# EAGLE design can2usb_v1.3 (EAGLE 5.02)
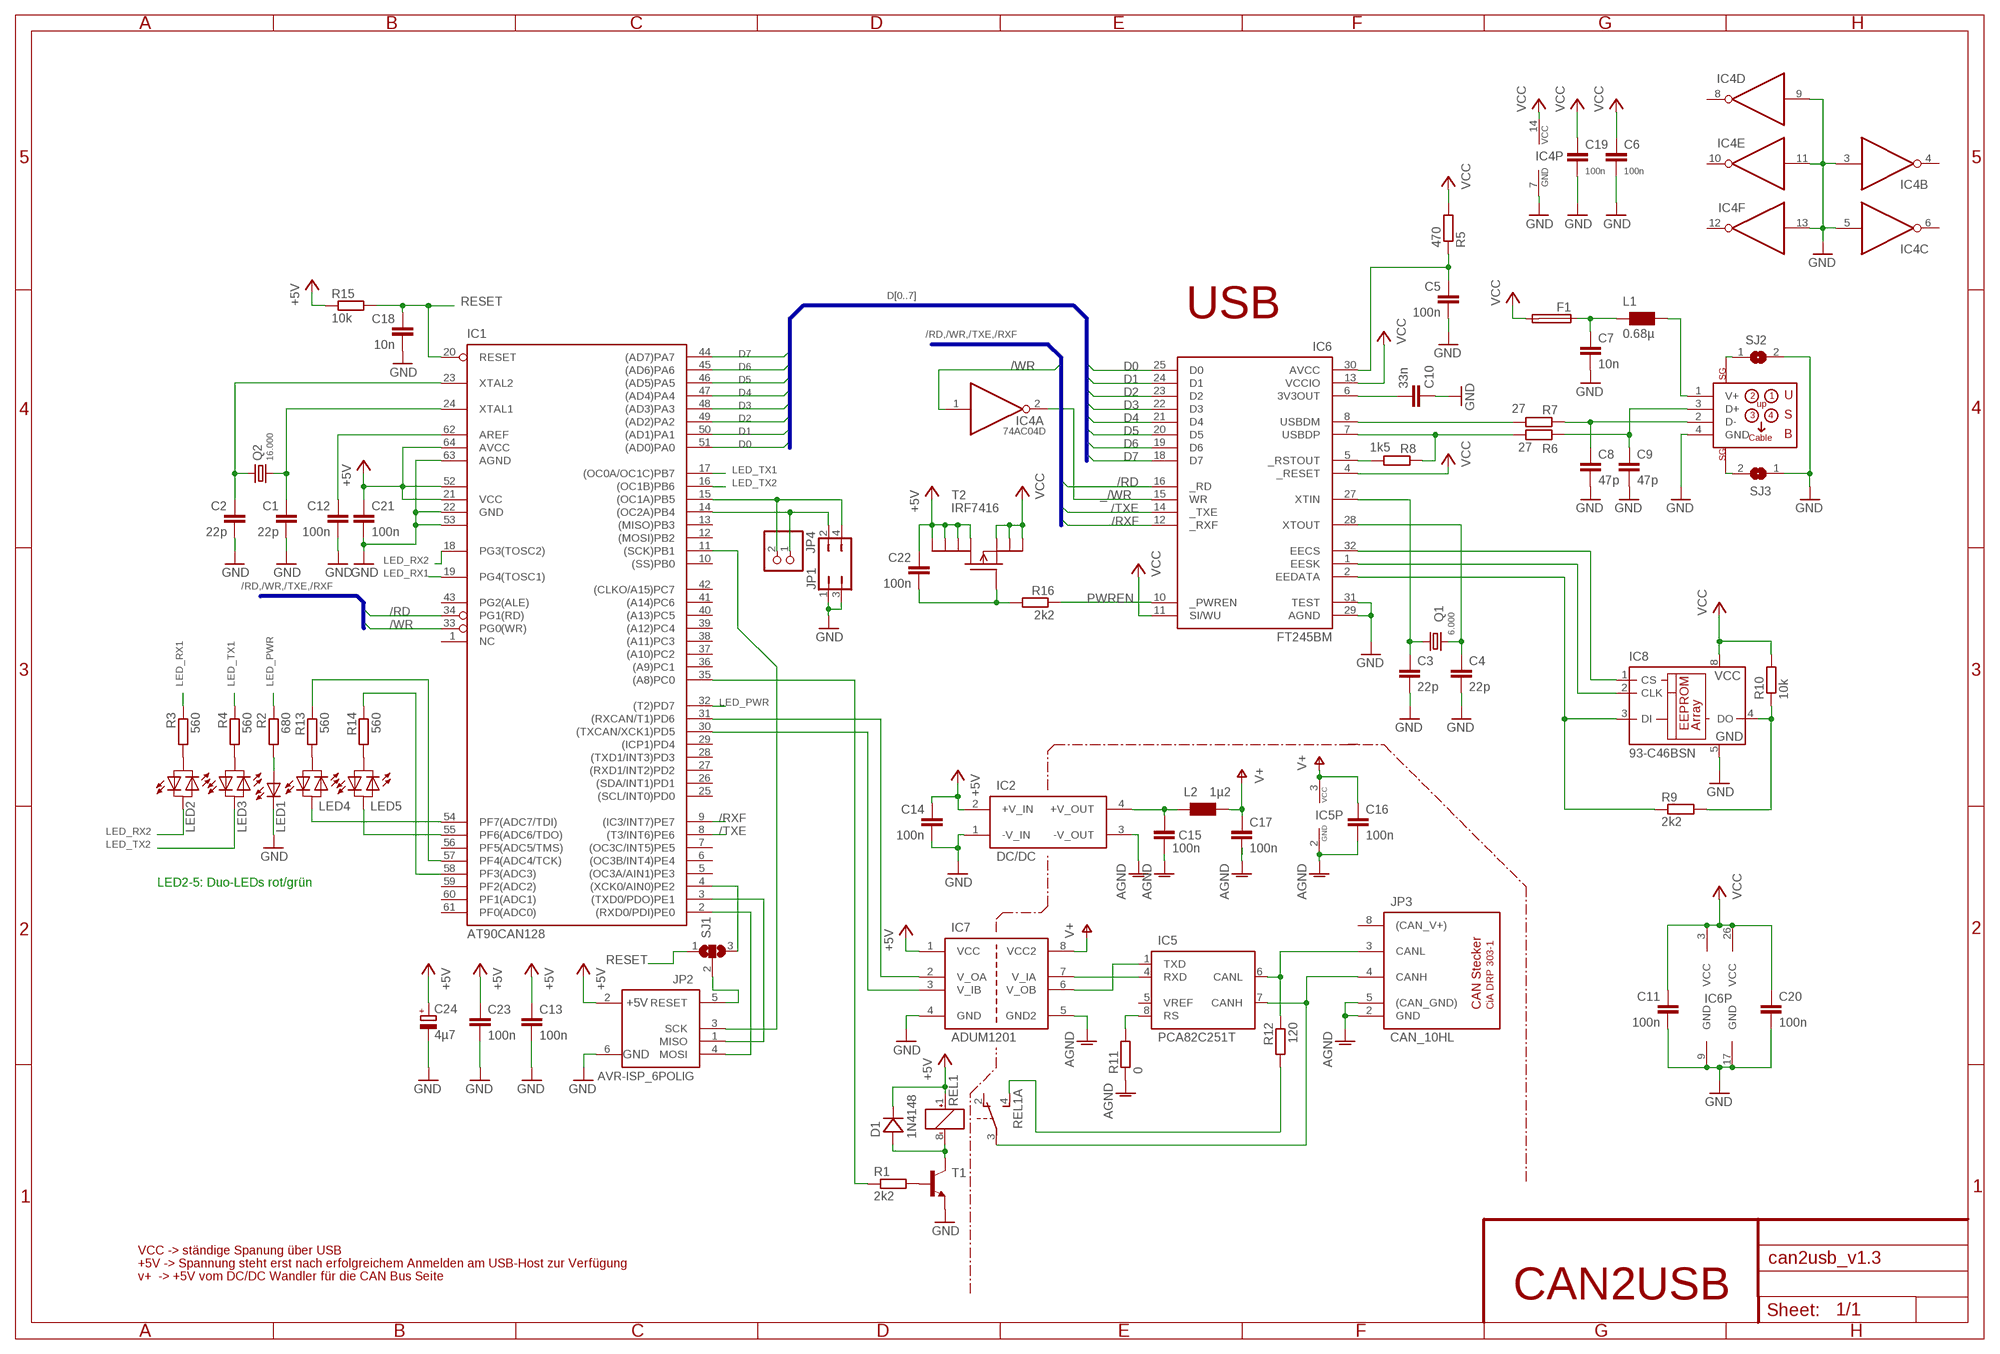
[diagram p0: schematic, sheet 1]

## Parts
C1  22p  C-EUC0805  [C0805]
C2  22p  C-EUC0805  [C0805]
C3  22p  C-EUC0805  [C0805]
C4  22p  C-EUC0805  [C0805]
C5  100n  C-EUC0805  [C0805]
C6  100n  C-EUC0805  [C0805]
C7  10n  C-EUC0805  [C0805]
C8  47p  C-EUC0805  [C0805]
C9  47p  C-EUC0805  [C0805]
C10  33n  C-EUC0805  [C0805]
C11  100n  C-EUC0805  [C0805]
C12  100n  C-EUC0805  [C0805]
C13  100n  C-EUC0805  [C0805]
C14  100n  C-EUC0805  [C0805]
C15  100n  C-EUC0805  [C0805]
C16  100n  C-EUC0805  [C0805]
C17  100n  C-EUC0805  [C0805]
C18  10n  C-EUC0805  [C0805]
C19  100n  C-EUC0805  [C0805]
C20  100n  C-EUC0805  [C0805]
C21  100n  C-EUC0805  [C0805]
C22  100n  C-EUC0805  [C0805]
C23  100n  C-EUC0805  [C0805]
C24  4µ7  CPOL-EU153CLV-0505  [153CLV-0505]
D1  1N4148  DIODESOD80C  [SOD80C]
F1  FUSE  [SMD-HASF]
IC1  AT90CAN128  AT90CAN128B  [SQFP-S-14X14-64]
IC2  DC/DC  [SIL4]
IC4  74AC04D  [SO14]
IC5  PCA82C251T  PCA82C250T  [SO08]
IC6  FT245BM  [LQFP-32]
IC7  ADUM1201  [SO08]
IC8  93-C46BSN  [SO-08]
JP1  JP2Q  [JP2Q]
JP2  AVR-ISP_6POLIG  [2X03]
JP3  CAN_10HL  [ML10L]
JP4  PINHD-1X2S  [1X02S]
L1  0.68µ  WE-KI_0805_B  [WE-KI_0805_B]
L2  1µ2  WE-KI_0805_B  [WE-KI_0805_B]
LED1  LED3MM  [LED3MM]
LED2  DUOLED  [LED3MM]
LED3  DUOLED  [LED3MM]
LED4  DUOLED  [LED3MM]
LED5  DUOLED  [LED3MM]
Q1  6.000  CRYTALSM49  [SM49]
Q2  16.000  CRYTALHC49U-V  [HC49U-V]
R1  2k2  R-EU_M0805  [M0805]
R2  680  R-EU_M0805  [M0805]
R3  560  R-EU_M0805  [M0805]
R4  560  R-EU_M0805  [M0805]
R5  470  R-EU_R0805  [R0805]
R6  27  R-EU_M0805  [M0805]
R7  27  R-EU_M0805  [M0805]
R8  1k5  R-EU_M0805  [M0805]
R9  2k2  R-EU_M0805  [M0805]
R10  10k  R-EU_M0805  [M0805]
R11  0  R-EU_M0805  [M0805]
R12  120  R-EU_R1206  [R1206]
R13  560  R-EU_M0805  [M0805]
R14  560  R-EU_M0805  [M0805]
R15  10k  R-EU_M0805  [M0805]
R16  2k2  R-EU_M0805  [M0805]
REL1  REL_2XUMDIL08SMD  [DIL08SMD]
SJ1  SJ2W  [SJ_2]
SJ2  SJ  [SJ]
SJ3  SJ  [SJ]
T1  NPNSOT23  [SOT23]
T2  IRF7416  MOSFET_P-KANAL_V1SO08  [SO08]
X1  USBCON-BB  [USBCONB]

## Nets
+5V: C13.1 C14.1 C21.1 C22.1 C23.1 C24.+ D1.C(C1) IC1.21(VCC) IC1.52(VCC1) IC1.64(AVCC) IC2.2(+V_IN) IC7.1(VCC) JP2.2(+5V) R15.1 REL1.1(SPULE:+) T2.5(D1) T2.6(D2) T2.7(D3) T2.8(D4)
/RD: IC1.34(PG1(RD)) IC6.16(_RD)
/RXF: IC1.9((IC3/INT7)PE7) IC6.12(_RXF)
/TXE: IC1.8((T3/INT6)PE6) IC6.14(_TXE)
/WR: IC1.33(PG0(WR)) IC4.1(A:I)
_/WR: IC4.2(A:O) IC6.15(WR)
_RXD: IC5.4(RXD) IC7.7(V_IA)
_TXD: IC5.1(TXD) IC7.6(V_OB)
AGND: C15.2 C16.2 C17.2 IC2.3(-V_OUT) IC5.2(GND) IC7.5(GND2) JP3.2(GND) JP3.5((CAN_GND)) R11.1
CANH: IC5.7(CANH) JP3.4(CANH) REL1.3(A:P)
CANL: IC5.6(CANL) JP3.3(CANL) R12.1
D0: IC1.51((AD0)PA0) IC6.25(D0)
D1: IC1.50((AD1)PA1) IC6.24(D1)
D2: IC1.49((AD2)PA2) IC6.23(D2)
D3: IC1.48((AD3)PA3) IC6.22(D3)
D4: IC1.47((AD4)PA4) IC6.21(D4)
D5: IC1.46((AD5)PA5) IC6.20(D5)
D6: IC1.45((AD6)PA6) IC6.19(D6)
D7: IC1.44((AD7)PA7) IC6.18(D7)
DM: C8.1 R7.1 X1.2(D-)
DP: C9.1 R6.1 X1.3(D+)
GND: C1.2 C2.2 C3.2 C4.2 C5.2 C6.2 C7.2 C8.2 C9.2 C10.1 C11.2 C12.2 C13.2 C14.2 C18.2 C19.2 C20.2 C21.2 C23.2 C24.- IC1.22(GND) IC1.53(GND1) IC1.63(AGND) IC2.1(-V_IN) IC4.3(B:I) IC4.5(C:I) IC4.7(P:GND) IC4.9(D:I) IC4.11(E:I) IC4.13(F:I) IC6.9(GND) IC6.17(GND) IC6.29(AGND) IC6.31(TEST) IC7.4(GND) IC8.5(GND) JP1.1 JP1.3 JP2.6(GND) LED1.K(C) SJ2.2 SJ3.1 T1.2(E) X1.4(GND)
LED_ERROR: IC1.57(PF4(ADC4/TCK)) R13.1
LED_OK: IC1.58(PF3(ADC3)) R14.1
LED_PWR: IC1.32((T2)PD7) R2.1
LED_RX1: IC1.19(PG4(TOSC1)) R3.1
LED_RX2: IC1.18(PG3(TOSC2)) LED2.K(C)
LED_TX1: IC1.17((OC0A/OC1C)PB7) R4.1
LED_TX2: IC1.16((OC1B)PB6) LED3.K(C)
MISO: IC1.3((TXD0/PDO)PE1) JP2.1(MISO)
N$1: JP2.5(RESET) SJ1.2
N$2: L1.1 X1.1(V+)
N$3: C22.2 R16.2 T2.4(G)
N$4: IC1.4((XCK0/AIN0)PE2) SJ1.3
N$5: R12.2 REL1.4(A:S)
N$6: D1.A(A1) REL1.8(SPULE:-) T1.3(C)
N$7: R1.2 T1.1(B)
N$8: C2.1 IC1.23(XTAL2) Q2.2
N$9: IC1.35((A8)PC0) R1.1
N$10: C1.1 IC1.24(XTAL1) Q2.1
N$11: C4.1 IC6.28(XTOUT) Q1.2
N$12: LED4.A R13.2
N$13: C3.1 IC6.27(XTIN) Q1.1
N$14: LED5.A R14.2
N$15: LED1.A R2.2
N$16: IC1.55(PF6(ADC6/TDO)) LED5.K(C)
N$17: IC1.54(PF7(ADC7/TDI)) LED4.K(C)
N$18: IC5.8(RS) R11.2
N$19: SJ2.1 X1.S2
N$20: SJ3.2 X1.S1
N$21: C7.1 F1.1 L1.2
N$22: C15.1 IC2.4(+V_OUT) L2.2
N$23: IC6.32(EECS) IC8.1(CS)
N$24: IC6.1(EESK) IC8.2(CLK)
N$25: IC8.4(DO) R9.2 R10.1
N$26: IC6.2(EEDATA) IC8.3(DI) R9.1
N$27: IC1.11((SCK)PB1) JP2.3(SCK)
N$28: C5.1 IC6.30(AVCC) R5.1
N$29: IC1.2((RXD0/PDI)PE0) JP2.4(MOSI)
N$30: C12.1 IC1.62(AREF)
N$31: IC6.8(USBDM) R7.2
N$32: IC6.7(USBDP) R6.2 R8.1
N$33: LED3.A R4.2
N$34: LED2.A R3.2
N$37: IC6.5(_RSTOUT) R8.2
N$38: C10.2 IC6.6(3V3OUT)
PWREN: IC6.10(_PWREN) R16.1
RESET: C18.1 IC1.20(RESET) R15.2 SJ1.1
RXCAN: IC1.31((RXCAN/T1)PD6) IC7.2(V_OA)
SW1: IC1.14((OC2A)PB4) JP1.2 JP4.1
SW2: IC1.15((OC1A)PB5) JP1.4 JP4.2
TXCAN: IC1.30((TXCAN/XCK1)PD5) IC7.3(V_IB)
V+: C16.1 C17.1 IC5.3(VCC) IC7.8(VCC2) L2.1
VCC: C6.1 C11.1 C19.1 C20.1 F1.2 IC4.14(P:VCC) IC6.3(VCC) IC6.4(_RESET) IC6.11(SI/WU) IC6.13(VCCIO) IC6.26(VCC) IC8.8(VCC) R5.2 R10.2 T2.1(S1) T2.2(S2) T2.3(S3)
Unconnected: IC1.1(NC) IC1.5((OC3A/AIN1)PE3) IC1.6((OC3B/INT4)PE4) IC1.7((OC3C/INT5)PE5) IC1.10((SS)PB0) IC1.12((MOSI)PB2) IC1.13((MISO)PB3) IC1.25((SCL/INT0)PD0) IC1.26((SDA/INT1)PD1) IC1.27((RXD1/INT2)PD2) IC1.28((TXD1/INT3)PD3) IC1.29((ICP1)PD4) IC1.36((A9)PC1) IC1.37((A10)PC2) IC1.38((A11)PC3) IC1.39((A12)PC4) IC1.40((A13)PC5) IC1.41((A14)PC6) IC1.42((CLKO/A15)PC7) IC1.43(PG2(ALE)) IC1.56(PF5(ADC5/TMS)) IC1.59(PF2(ADC2)) IC1.60(PF1(ADC1)) IC1.61(PF0(ADC0)) IC4.4(B:O) IC4.6(C:O) IC4.8(D:O) IC4.10(E:O) IC4.12(F:O) IC5.5(VREF) JP3.8((CAN_V+)) REL1.2(A:O) REL1.5(B:S) REL1.6(B:P) REL1.7(B:O)

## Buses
D[0..7]
/RD,/WR,/TXE,/RXF

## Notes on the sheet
- USB
- LED2-5: Duo-LEDs rot/grün
- VCC -> ständige Spanung über USB
- +5V -> Spannung steht erst nach erfolgreichem Anmelden am USB-Host zur Verfügung
- v+  -> +5V vom DC/DC Wandler für die CAN Bus Seite
- CAN2USB

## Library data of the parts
C1-C23 = rcl:C-EU: CAPACITOR, European symbol
C24 = rcl:CPOL-EU: POLARIZED CAPACITOR, European symbol
D1 = BV_dioden:DIODE
F1 = rca_sontiges:FUSE: SMD Fuse
IC1 = avr:AT90CAN128: MICROCONTROLLER 128 Kbytes FLASH 4 Kbytes SRAM 4 Kbytes EEPROM DUAL USART 8-channel 10 bit ADC CAN 2.0 A&B Interface
IC2 = rca_spgversorgung:DC/DC
IC4 = 74xx-eu:74*04: Hex INVERTER
IC5 = andereBauteile:PCA82C250: PCA82C250 CAN Bustreiber
IC6 = ftdi:FT245BM: USB FIFO 2nd Generation USB FIFO (USB <-> Parallel)
IC7 = rca_opto:ADUM1201: ADuM1201 Dual-Channel Digital Isolators zu beziehen per Sample oder bei Farnell
IC8 = microchip:93-*: Serial EEPROM 512 x 8 bit/256 x 16 bit/1 K/4 K, 5.0 V, Microwire
JP1 = jumper:JP2Q: JUMPER
JP2 = stecker-definitionen:AVR-ISP_6POLIG: ISP (In System Programming) Stecker für AVRs Über diesen Anschluß kann ein AVR mit einem Standard ISP-Kabel direkt an einen Parallelport des PC´s angeschlossen und programmiert werden.
JP3 = stecker-definitionen:CAN_: CAN Stecker nach CiA DRP 303-1
JP4 = pinhead:PINHD-1X2: PIN HEADER
L1 L2 = wuerth-elektronik:WE-KI: SMD Wire Wound Ceramic Inductor WE-KI
LED1 = led:LED: LED
LED2-LED5 = rca_opto:DUOLED
Q1 Q2 = crystal:CRYTAL: CRYSTAL
R1-R16 = rcl:R-EU_: RESISTOR, European symbol
REL1 = BV_sonstiges:REL_2XUM
SJ1 = jumper:SJ2W: SMD solder JUMPER
SJ2 SJ3 = jumper:SJ: SMD solder JUMPER
T1 = BV_transistoren:NPN
T2 = BV_transistoren:MOSFET_P-KANAL_V1
X1 = USB:USBCON-B: USB-Contector B-Type

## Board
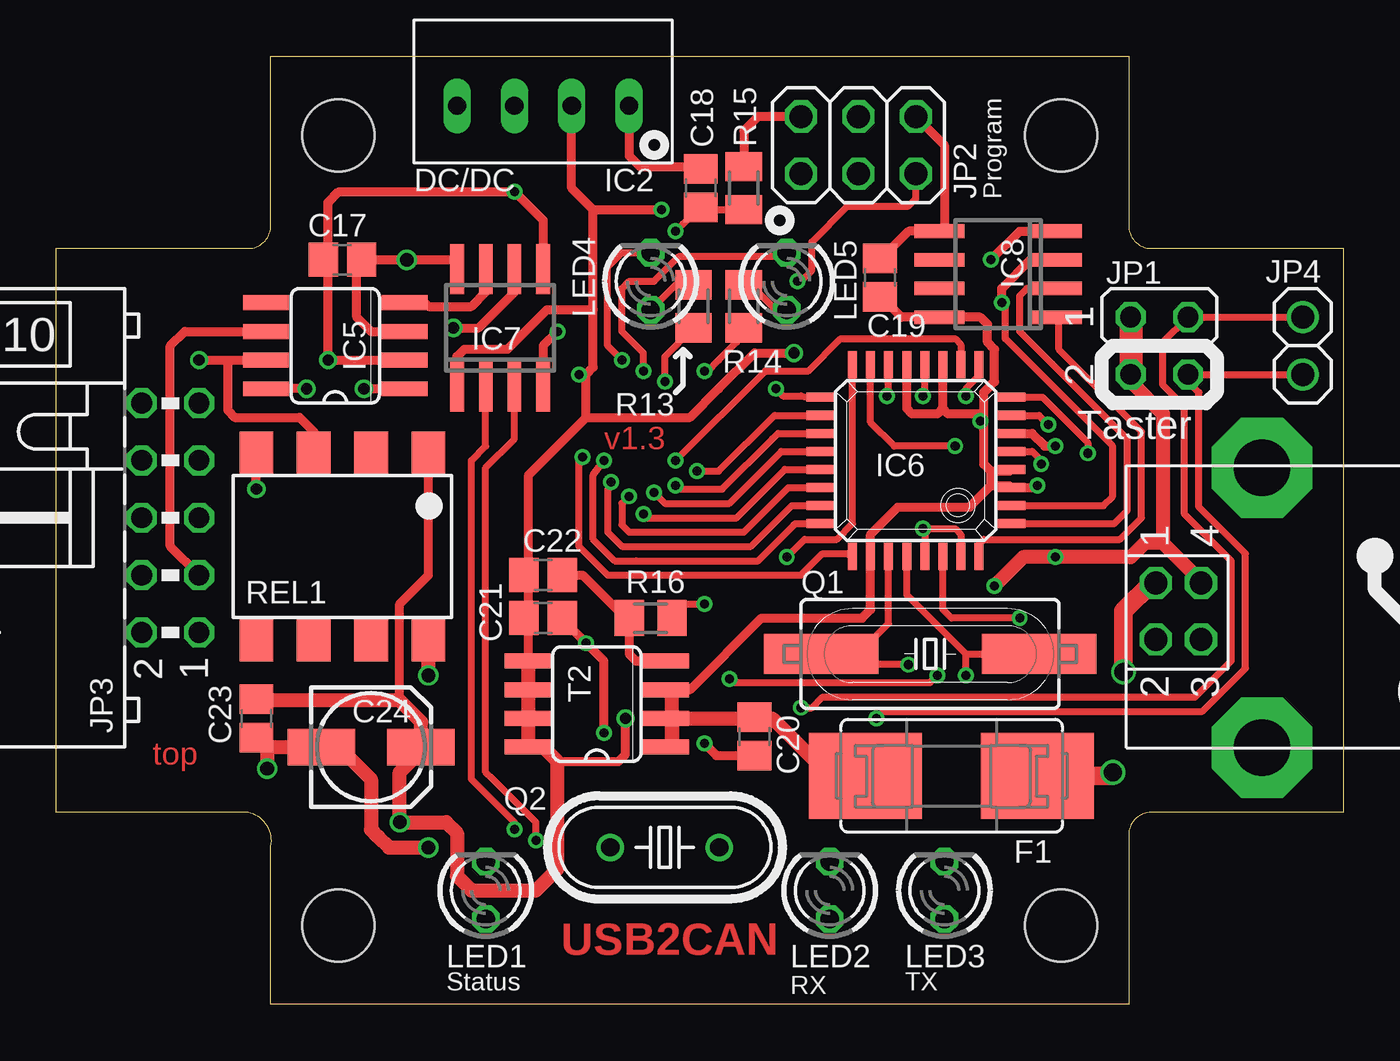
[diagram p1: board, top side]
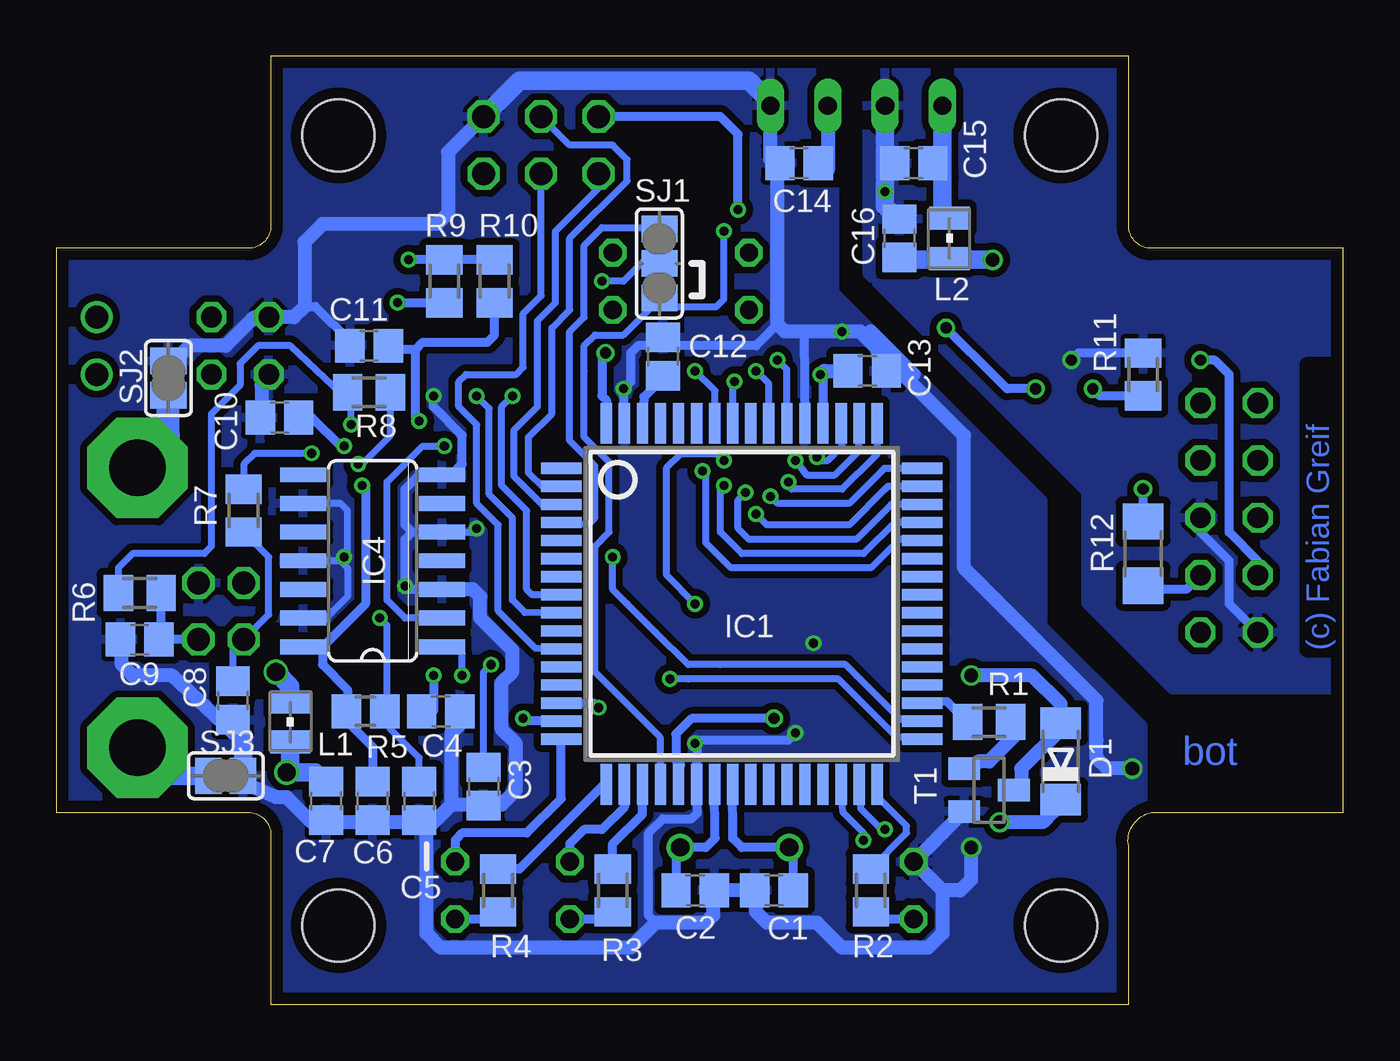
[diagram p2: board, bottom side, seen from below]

Size 57 x 42 mm. Coordinates in mm from the lower left corner, seen from the top.
Outline: 0,33.5 8.5,33.5 arc90 9.5,34.5 9.5,42 47.5,42 47.5,34.5 arc90 48.5,33.5 57,33.5 57,8.5 48.5,8.5 arc90 47.5,7.5 47.5,0 9.5,0 9.5,7 arc90 8.5,8.5 0,8.5 0,33.5
Copper layers (1*16): Top 0.035mm / dielectric 1.5mm / Bottom 0.035mm
Design rules "PCB-POOL": minimum track width 6mil, minimum drill 12mil, track to track 6mil, track to pad 6mil, pad to pad 6mil, via to via 6mil, smd to smd 6mil, copper to edge 20mil, drill to drill 8mil, minimum pad ring 8mil, minimum via ring 6mil, stop-mask expansion 3mil, vias tented up to drill 20mil, thermal gap 8mil
Holes 3.2 mm at 12.5,38.5 44.5,38.5 12.5,3.5 44.5,3.5

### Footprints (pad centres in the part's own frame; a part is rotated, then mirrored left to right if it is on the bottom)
C0805 = smd 1.3 x 1.5: 1 -0.85,0; 2 0.85,0
153CLV-0505 = smd 3 x 1.6: + 2.2,0; - -2.2,0
SOD80C = smd 1.4 x 1.8: A 1.7,0; C -1.7,0
SMD-HASF = smd 5 x 3.81: 1 -3.81,0; 2 3.81,0
SQFP-S-14X14-64 = smd 0.5 x 1.8: 1 -6,-8; 2 -5.2,-8; 3 -4.4,-8; 4 -3.6,-8; 5 -2.8,-8; 6 -2,-8; 7 -1.2,-8; 8 -0.4,-8; 9 0.4,-8; 10 1.2,-8; 11 2,-8; 12 2.8,-8; 13 3.6,-8; 14 4.4,-8; 15 5.2,-8; 16 6,-8; 33 6,8; 34 5.2,8; 35 4.4,8; 36 3.6,8; 37 2.8,8; 38 2,8; 39 1.2,8; 40 0.4,8; 41 -0.4,8; 42 -1.2,8; 43 -2,8; 44 -2.8,8; 45 -3.6,8; 46 -4.4,8; 47 -5.2,8; 48 -6,8 | smd 1.8 x 0.5: 17 8,-6; 18 8,-5.2; 19 8,-4.4; 20 8,-3.6; 21 8,-2.8; 22 8,-2; 23 8,-1.2; 24 8,-0.4; 25 8,0.4; 26 8,1.2; 27 8,2; 28 8,2.8; 29 8,3.6; 30 8,4.4; 31 8,5.2; 32 8,6; 49 -8,6; 50 -8,5.2; 51 -8,4.4; 52 -8,3.6; 53 -8,2.8; 54 -8,2; 55 -8,1.2; 56 -8,0.4; 57 -8,-0.4; 58 -8,-1.2; 59 -8,-2; 60 -8,-2.8; 61 -8,-3.6; 62 -8,-4.4; 63 -8,-5.2; 64 -8,-6
SIL4 = drill 0.813 long: 1 -3.81,0; 2 -1.27,0; 3 1.27,0; 4 3.81,0
SO14 = smd 0.66 x 2.032: 1 -3.81,-3.073; 2 -2.54,-3.073; 3 -1.27,-3.073; 4 0,-3.073; 5 1.27,-3.073; 6 2.54,-3.073; 7 3.81,-3.073; 8 3.81,3.073; 9 2.54,3.073; 10 1.27,3.073; 11 0,3.073; 12 -1.27,3.073; 13 -2.54,3.073; 14 -3.81,3.073
SO08 = smd 0.66 x 2.032: 1 -1.905,-3.073; 2 -0.635,-3.073; 3 0.635,-3.073; 4 1.905,-3.073; 5 1.905,3.073; 6 0.635,3.073; 7 -0.635,3.073; 8 -1.905,3.073
LQFP-32 = smd 0.4 x 1.2: 1 -2.8,-4.25; 2 -2,-4.25; 3 -1.2,-4.25; 4 -0.4,-4.25; 5 0.4,-4.25; 6 1.2,-4.25; 7 2,-4.25; 8 2.8,-4.25; 17 2.8,4.25; 18 2,4.25; 19 1.2,4.25; 20 0.4,4.25; 21 -0.4,4.25; 22 -1.2,4.25; 23 -2,4.25; 24 -2.8,4.25 | smd 1.2 x 0.4: 9 4.25,-2.8; 10 4.25,-2; 11 4.25,-1.2; 12 4.25,-0.4; 13 4.25,0.4; 14 4.25,1.2; 15 4.25,2; 16 4.25,2.8; 25 -4.25,2.8; 26 -4.25,2; 27 -4.25,1.2; 28 -4.25,0.4; 29 -4.25,-0.4; 30 -4.25,-1.2; 31 -4.25,-2; 32 -4.25,-2.8
SO08' = smd 0.6 x 2.2: 1 -1.905,-2.6; 2 -0.635,-2.6; 3 0.635,-2.6; 4 1.905,-2.6; 5 1.905,2.6; 6 0.635,2.6; 7 -0.635,2.6; 8 -1.905,2.6
SO-08 = smd 0.6 x 2.2: 1 -1.905,-2.6; 2 -0.635,-2.6; 3 0.635,-2.6; 4 1.905,-2.6; 5 1.905,2.6; 6 0.635,2.6; 7 -0.635,2.6; 8 -1.905,2.6
JP2Q = drill 0.914 octagon: 1 -1.27,-1.27; 2 -1.27,1.27; 3 1.27,-1.27; 4 1.27,1.27
2X03 = drill 1.016 octagon: 1 -2.54,-1.27; 2 -2.54,1.27; 3 0,-1.27; 4 0,1.27; 5 2.54,-1.27; 6 2.54,1.27
ML10L = drill 0.914 octagon: 1 -5.08,-1.27; 2 -5.08,1.27; 3 -2.54,-1.27; 4 -2.54,1.27; 5 0,-1.27; 6 0,1.27; 7 2.54,-1.27; 8 2.54,1.27; 9 5.08,-1.27; 10 5.08,1.27
1X02S = drill 1.016 round: 1 -1.27,0; 2 1.27,0
WE-KI_0805_B = smd 1.02 x 1.78: 1 -0.89,0; 2 0.89,0
LED3MM = drill 0.813 octagon: A -1.27,0; K 1.27,0
SM49 = smd 5.08 x 1.778: 1 -4.826,0; 2 4.826,0
HC49U-V = drill 0.813 round: 1 -2.413,0; 2 2.413,0
M0805 = smd 1.3 x 1.6: 1 -0.95,0; 2 0.95,0
R0805 = smd 1.3 x 1.5: 1 -0.85,0; 2 0.85,0
R1206 = smd 1.6 x 1.803: 1 -1.422,0; 2 1.422,0
DIL08SMD = smd 1.5 x 1.9: 1 -3.81,-4.15; 2 -1.27,-4.15; 3 1.27,-4.15; 4 3.81,-4.15; 5 3.81,4.15; 6 1.27,4.15; 7 -1.27,4.15; 8 -3.81,4.15
SJ_2 = smd 1.168 x 1.6: 1 -1.524,0; 2 0,0; 3 1.524,0
SJ = smd 1.168 x 1.6: 1 -0.762,0; 2 0.762,0
SOT23 = smd 1 x 1.4: 1 -0.95,-1.1; 2 0.95,-1.1; 3 0,1.1
USBCONB = drill 1.016 octagon: 1 7.3,4.7; 2 4.8,4.7; 3 4.8,2.7; 4 7.3,2.7 | drill 2.5 pad 4.445 octagon: S1 0,0; S2 12.4,0

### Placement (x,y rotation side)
C1  25.21,5.05 180 bottom
C2  28.7,5.05 0 bottom
C3  38.07,9.65 270 bottom
C4  39.97,12.99 0 bottom
C5  40.93,9.02 270 bottom
C6  42.99,9.02 270 bottom
C7  45.05,9.02 270 bottom
C8  49.18,13.46 270 bottom
C9  53.31,16.16 180 bottom
C10  47.12,26 0 bottom
C11  43.15,29.18 180 bottom
C12  30.13,28.7 90 bottom
C13  21.08,28.07 0 bottom
C14  24.1,37.28 180 bottom
C15  19.02,37.28 180 bottom
C16  19.65,33.94 90 bottom
C17  12.67,32.99 180 top
C18  28.54,36.16 90 top
C19  36.48,32.2 90 top
C20  30.92,11.88 270 top
C21  21.56,17.11 0 top
C22  21.56,19.02 0 top
C23  8.86,12.67 270 top
C24  13.94,11.4 0 top
D1  12.51,10.76 90 bottom
F1  39.66,10.13 180 top
IC1  26.64,17.75 270 bottom
IC2  21.56,39.82 180 top
IC4  42.99,19.65 90 bottom
IC5  12.35,29.18 90 top
IC6  38.07,24.1 90 top
IC7  ADUM1201  [SO08']  19.65,29.97 0 top
IC8  41.72,32.35 90 top
JP1  48.86,29.18 270 top
JP2  35.53,38.07 0 top
JP3  5.05,21.56 90 top
JP4  55.21,29.18 270 top
L1  46.64,12.51 270 bottom
L2  17.43,33.94 90 bottom
LED1  19.02,5.05 90 top
LED2  34.26,5.05 90 top
LED3  39.34,5.05 90 top
LED4  26.32,32.04 90 top
LED5  32.35,32.04 90 top
Q1  38.7,15.53 0 top
Q2  26.96,6.95 0 top
R1  15.69,12.51 0 bottom
R2  20.92,5.05 270 bottom
R3  32.35,5.05 270 bottom
R4  37.43,5.05 270 bottom
R5  43.31,12.99 180 bottom
R6  53.31,18.23 180 bottom
R7  48.7,21.88 90 bottom
R8  43.15,27.12 0 bottom
R9  39.81,32.04 90 bottom
R10  37.59,32.04 270 bottom
R11  8.86,27.91 270 bottom
R12  8.86,19.97 90 bottom
R13  28.23,30.93 90 top
R14  30.45,30.93 90 top
R15  30.45,36.16 270 top
R16  26.32,17.11 180 top
REL1  12.67,20.29 180 top
SJ1  30.29,32.83 90 bottom
SJ2  52.04,27.75 90 bottom
SJ3  49.5,10.13 180 bottom
T1  15.68,9.49 270 bottom
T2  23.94,13.3 90 top
X1  53.41,11.37 90 top

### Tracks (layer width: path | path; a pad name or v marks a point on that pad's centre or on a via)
+5V  (via drill 0.4, 0.5, 0.6)
  Top 0.406: REL1.1 16.48,19.02 15.21,17.75 15.21,13.46 | v25.21,12.67 25.21,12.19 25.21,11.08 24.89,10.76 22.19,10.76 | v25.21,12.67 | 23.46,27.91 23.78,28.23 23.78,30.77 | 23.78,30.77 23.78,35.21 | 23.78,35.21 22.83,36.16 IC2.2 22.83,40.13 | 20.92,15.21 20.92,16.8 20.61,17.11 C21.1 20.92,17.11 20.92,19.02 | 23.46,26 23.46,27.91 | 23.46,27.91 v23.15,27.91 | 29.34,27.27 28.07,26 23.46,26 | 29.34,27.27 | 29.34,27.27 30.92,28.86 v32.67,28.86 | C22.1 20.71,19.23 20.92,19.02 | 20.92,19.02 20.92,23.46 23.46,26 | 8.86,13.46 C23.1 | JP2.2 31.08,39.34 30.45,38.7 R15.1 | 23.78,35.21 v26.8,35.21 | IC7.1 17.75,28.7 18.07,29.02 19.97,29.02 21.72,30.77 23.78,30.77
  Top 0.61: 20.92,11.4 T2.8 | 20.92,11.4 20.92,12.67 | 20.92,12.67 T2.7 | 20.92,12.67 20.92,13.94 | 20.92,13.94 T2.6 | T2.5 20.92,15.21 20.92,13.94 | 20.92,11.4 21.56,11.4 22.19,10.76 22.19,6 21.24,5.05 18.38,5.05 17.75,5.68 17.75,7.59 17.27,8.06 v15.21,8.06 15.21,10.29 16.32,11.4 C24.+ 16.14,11.53 16.16,11.56 16.16,12.51 15.21,13.46 8.86,13.46
  Bottom 0.406: v25.21,12.67 28.86,12.67 29.55,11.98 29.55,10.82 29.34,10.6 29.39,10.55 IC1.21 | IC1.52 23.04,27.8 v23.15,27.91 23.1,27.86 | IC1.64 32.64,26.76 32.83,26.96 32.83,28.7 32.7,28.83 32.64,28.83 v32.67,28.86 | v26.8,35.21 26.8,38.54 27.59,39.34 JP2.2
  Bottom 0.61: C14.1 23.25,37.01 22.83,36.96 IC2.2 | D1.C 12.83,8.54 13.3,8.06 v15.21,8.06 | C13.1 22.99,28.07 v23.15,27.91
/RD  (via drill 0.4)
  Top 0.305: IC6.16 35.27,21.3 34.58,20.61 33.15,20.61 v32.35,19.81
  Bottom 0.305: IC1.34 19.62,12.63 21.56,14.57 22.03,15.05 27.59,15.05 29.02,15.05 30.45,16.48 31.72,17.75 32.35,18.38 | 32.35,18.38 v32.35,19.81 | 32.35,18.38
/RXF  (via drill 0.4)
  Top 0.305: IC6.12 38.47,27.04 v38.39,26.96
  Bottom 0.305: IC1.9 36.25,17.35 36.8,17.91 36.8,21.56 37.83,22.59 37.83,26.4 v38.39,26.96
/TXE  (via drill 0.4)
  Top 0.305: IC6.14 36.87,27.03 v36.8,26.96
  Bottom 0.305: IC1.8 35.92,18.14 36.16,18.38 36.16,21.88 37.27,22.99 37.27,26.48 v36.8,26.96
/WR  (via drill 0.4)
  Top 0.305: v29.81,14.41 29.97,14.26 33.31,14.26 33.62,14.26 38.7,14.26 v39.02,14.57
  Bottom 0.305: IC1.33 19.78,11.84 22.35,14.41 29.02,14.41 29.5,14.41 v29.81,14.41 | v39.02,14.57 39.02,15.53 39.34,15.84 IC4.1
  Bottom 0.406: IC4.1 39.66,15.84
_/WR  (via drill 0.4)
  Top 0.305: IC6.15 36.07,25.78 37.12,24.73 v39.81,24.73
  Bottom 0.305: 39.34,17.11 IC4.2 41.56,17.11 42.35,17.91 42.35,23.15 40.77,24.73 v39.81,24.73
_RXD
  Top 0.406: IC7.7 19.02,31.56 18.38,30.92 16.48,30.92 16.32,31.08 IC5.4
_TXD  (via drill 0.5)
  Top 0.406: 15.84,27.27 IC5.1 v13.62,27.27 | v17.59,29.97 18.7,29.97 20.29,31.56 IC7.6 20.29,32.67
  Bottom 0.406: v13.62,27.27 14.89,27.27 15.37,27.75 v17.59,29.97
AGND  (via drill 0.4, 0.5)
  Top 0.406: IC5.2 v12.03,28.54 12.03,32.99 | IC7.5 21.56,34.73 v20.29,36 12.51,36 12.03,35.53 12.03,32.99 | 12.03,32.99 C17.2
  Bottom 0.406: IC2.3 20.29,38.7 | JP3.2 5.05,17.75 5.05,19.65 6.32,20.92 JP3.5 | v12.03,28.54 11.72,28.86 9.02,28.86 8.86,28.7 R11.1
  Bottom 0.61: 20.29,36.64 C15.2
  Bottom 0.813: 20.29,38.86 IC2.3 20.29,36.64 v20.29,36 20.29,35.37 19.97,35.05 C16.2
  pour Bottom (isolate 0.305): -1.3,13.94 7.59,13.94 11.4,17.75 11.4,22.67 21.08,32.35 21.08,43.15 -1.3,43.15
CANH  (via drill 0.5)
  Top 0.406: v6.32,28.54 7.59,28.54 | 7.59,28.54 IC5.7 | REL1.3 11.4,25.37 10.76,26 7.91,26 7.59,26.32 7.59,28.54
  Bottom 0.406: v6.32,28.54 5.68,28.54 5.05,27.91 5.05,20.92 3.78,19.65 JP3.4
CANL
  Top 0.406: IC5.6 5.68,29.81 5.05,29.18 5.05,20.29 JP3.3
  Bottom 0.406: R12.1 8.86,18.38 6.95,18.38 JP3.3
D0  (via drill 0.4)
  Top 0.305: IC6.25 35.17,19.85 35.05,19.97 33.94,19.97 32.99,19.02 24.42,19.02 23.15,20.29 23.15,24.1 v23.3,24.26
  Bottom 0.305: IC1.51 22.31,25.48 22.19,25.37 22.19,24.73 22.83,24.1 23.15,24.1 v23.3,24.26
D1  (via drill 0.4)
  Top 0.305: IC6.24 32.73,21.3 32.67,21.24 31.08,19.65 25.69,19.65 24.73,19.65 23.78,20.61 23.78,23.46 v24.26,24.1
  Bottom 0.305: 21.56,24.42 22.51,23.46 23.78,23.46 v24.26,24.1 | 21.56,24.42 21.52,24.45 | IC1.50 21.44,24.54 21.56,24.42
D2  (via drill 0.4)
  Top 0.305: IC6.23 32.58,22.1 30.77,20.29 25.05,20.29 24.42,20.92 24.42,22.83 v24.57,23.15
  Bottom 0.305: 20.76,24.26 22.19,22.83 24.42,22.83 v24.57,23.15 | 20.76,24.26 20.73,24.29 | 20.76,24.26 | IC1.49 20.64,24.38 20.76,24.26
D3  (via drill 0.4)
  Top 0.305: IC6.22 32.42,22.9 30.45,20.92 25.37,20.92 25.05,21.24 25.05,22.19 v25.37,22.51
  Bottom 0.305: 20.42,23.65 21.88,22.19 25.05,22.19 v25.37,22.51 | IC1.48 20.32,23.75 20.42,23.65 | 20.42,23.65 | 20.42,23.65 20.45,23.62
D4  (via drill 0.4)
  Top 0.305: IC6.21 32.27,23.7 30.13,21.56 26.16,21.56 v26,21.72
  Bottom 0.305: 20.29,22.83 21.88,21.24 25.53,21.24 25.69,21.4 v26,21.72 | 20.29,22.83 20.25,22.87 | IC1.47 20.17,22.95 20.29,22.83
D5  (via drill 0.4)
  Top 0.305: IC6.20 32.12,24.5 32.04,24.42 29.81,22.19 26.96,22.19 v26.48,22.67
  Bottom 0.305: 20.13,22.03 20.09,22.08 | 20.13,22.03 21.56,20.61 26.32,20.61 26.8,21.08 26.8,22.35 v26.48,22.67 | 20.13,22.03 | IC1.46 20.02,22.15 20.13,22.03
D6  (via drill 0.4)
  Top 0.305: IC6.19 31.97,25.3 31.72,25.05 29.5,22.83 27.59,22.83 v27.43,22.99
  Bottom 0.305: v27.43,22.99 27.59,22.99 27.59,20.92 26.64,19.97 21.24,19.97 19.86,21.35 IC1.45
D7  (via drill 0.4)
  Top 0.305: IC6.18 31.81,26.1 29.34,23.62 | v28.38,23.62 29.34,23.62 | 29.34,23.62
  Bottom 0.305: IC1.44 18.92,20.5 19.02,20.61 19.65,20.61 20.92,19.34 27.11,19.34 28.23,20.45 28.23,23.3 28.23,23.46 v28.38,23.62
DM
  Bottom 0.305: R7.1 47.59,19.81 47.59,17.27 X1.2 | X1.2 | C8.1 49.18,15.68 X1.2
DP
  Bottom 0.406: X1.3 50.76,16.17 50.77,16.16 52.36,16.16 | 52.36,16.16 C9.1 | R6.1 52.36,16.16
GND  (via drill 0.4, 0.6)
  Top 0.305: 38.47,20.85 IC6.29 | 38.47,20.85 38.7,21.08 39.81,21.08 40.07,20.83 IC6.31 | IC6.17 33.25,26.9 32.99,26.96 32.19,26.96 v31.88,27.27 | IC6.9 40.87,27.85 40.29,27.27 v40.29,26.96 | 38.47,20.85 38.46,20.85 v38.39,21.08
  Top 0.406: v22.19,29.81 21.56,29.18 IC7.4 | C18.2 28.54,37.12 25.84,37.12 25.37,37.59 IC2.1 | v24.26,12.03 24.26,15.21 v23.46,16 22.51,16.95 C21.2 | JP2.6 39.34,38.07 39.34,34.42 39.18,34.26 IC8.5 37.75,34.26 36.48,32.99 | 36.48,32.99 | 36.48,32.99 C19.2 | JP1.3 47.59,27.59 | C20.2 29.23,11.02 v28.7,11.56
  Top 0.61: 50.73,18.67 X1.4 | 50.77,18.7 49.02,20.45 | 47.59,27.59 49.02,26.16 49.02,20.45 | 49.02,20.45 48.23,20.45 47.59,19.81 v44.26,19.81 42.83,19.81 v41.56,18.54 | C23.2 8.91,11.82 9.33,11.4 | 9.33,11.4 C24.- 12.51,11.4 13.94,9.97 13.94,7.75 14.26,7.43 14.73,6.95 v16.48,6.95 | 9.33,11.4 v9.33,10.45
  Top 0.813: 50.77,18.7 50.73,18.67
  Top 1.016: 47.43,30.45 | JP1.1 47.43,30.45 | JP1.3 | JP1.3 47.59,30.29 47.43,30.45
  Bottom 0.305: IC1.63 31.92,25.65 31.88,25.69 | 39.34,20.92 IC4.5 39.97,20.92 38.54,20.92 v38.39,21.08 | 40.93,23.46 39.5,23.46 | IC4.9 44.42,22.19 44.1,21.88 44.1,19.97 44.42,19.65 | 44.42,19.65 IC4.11 | IC4.13 45.05,17.11 44.1,18.07 44.1,19.34 44.42,19.65 | v44.26,19.81 | v44.26,19.81 44.42,19.65
  Bottom 0.406: 31.88,25.69 v31.88,27.27 31.56,27.59 31.56,28.86 31.24,29.18 30.45,29.18 | 30.45,29.18 C12.2 | v24.26,12.03 24.57,11.72 28.54,11.72 v28.7,11.56 28.61,11.34 IC1.22 28.61,8.48 28.86,8.22 30.13,8.22 30.77,7.59 30.77,3.94 30.45,3.62 | 25.05,30.13 26,29.18 30.45,29.18 | 24.1,29.81 23.88,29.6 IC1.53 | 39.97,18.38 41.4,18.38 v41.56,18.54 41.56,20.61 41.24,20.92 | 41.24,20.92 39.97,20.92 | IC4.7 40.93,23.46 41.56,22.83 41.56,21.24 41.24,20.92 | v40.29,26.96 40.29,26.48 39.02,25.21 39.02,23.94 39.5,23.46 | 41.24,20.92 | 45.37,8.06 45.05,8.08 | 45.05,8.08 C6.2 | 46.01,30.92 45.53,30.92 43.94,29.34 C11.2 | 45.05,8.08 45.05,8.22 C7.2 | JP1.3
  Bottom 0.61: 49.18,12.03 48.86,12.03 48.74,11.91 48.7,11.87 48.7,9.81 47.28,9.18 46.8,9.18 45.69,8.06 45.37,8.06 41.72,8.06 41.4,8.06 C5.2 40.93,8.07 40.93,8.06 40.61,7.75 | 49.18,12.03 51.88,14.57 53.63,14.57 54.1,15.05 54.1,15.84 54.26,16.16 C9.2 | 31.56,2.51 39.97,2.51 40.61,3.14 40.61,7.75 | 31.56,2.51 30.45,3.62 28.23,3.62 27.91,3.94 27.91,5.05 C2.2 C1.2 26,5.05 26,4.1 25.53,3.62 23.3,3.62 22.19,2.51 18.38,2.51 17.75,3.14 17.75,5.05 | 31.56,2.51 | 17.75,5.05 LED1.K | LED1.K | LED1.K 18.22,7.11 | JP2.6 39.66,37.75 39.66,35.05 40.13,34.58 45.21,34.58 46.01,33.78 46.01,30.92 46.48,30.45 JP1.1 | IC4.3 39.97,18.38 38.54,18.38 38.23,18.07 38.23,17.11 36.8,15.68 36.8,14.73 37.27,14.26 37.27,12.19 36.64,11.56 36.64,9.49 37.27,8.86 38.07,8.86 C3.2 38.33,8.8 | 49.18,12.35 49.18,12.03 | C10.1 47.91,26 47.91,27.43 47.59,27.75 JP1.3 | 25.21,37.27 25.37,37.43 IC2.1 | 25.21,37.27 25.05,37.59 25.05,30.13 24.73,29.81 24.1,29.81 v22.19,29.81 21.4,29.81 19.65,28.07 | C14.2 24.95,36.7 25.21,37.27 | 16.8,19.34 16.8,25.21 19.65,28.07 | 51.75,28.51 51.09,29.18 49.5,29.18 48.39,30.29 | 48.39,30.29 | 48.39,30.29 48.23,30.45 JP1.1 | JP1.1 | 40.61,7.75 39.5,8.86 | C4.2 38.96,13.25 38.86,12.67 39.5,12.03 39.5,8.86 | 40.61,7.75 | 38.33,8.8 37.97,8.8 | 38.33,8.8 38.23,8.86 39.5,8.86 | 18.22,7.11 | 18.22,7.11 17.75,7.59 | T1.2 17.26,8.08 17.75,7.59 | 17.75,7.59 | v16.48,6.95 16.48,5.52 16.95,5.05 17.75,5.05 | 16.8,19.34 | 16.8,19.34 10.92,13.46 10.92,11.72 10.92,10.92 10.45,10.45 v9.33,10.45 | 19.65,28.07 | 19.65,28.07 C13.2 20.13,28.07 | 19.02,27.91 20.92,29.81 20.29,27.91 20.13,28.07 | 20.13,28.07 19.97,28.23
  Bottom 0.813: IC2.1 25.37,39.97 26.32,40.93 36.48,40.93 JP2.6 | 54.1,15.84 54.1,16.16 | C8.2 49.18,12.35 48.74,11.91 SJ3.1
  pour Bottom (isolate 0.305, rank 2): 22.51,43.15 58.39,43.15 58.39,-1.3 8.86,-1.3 8.86,12.35 13.3,16.8 13.3,22.35 22.51,31.56
LED_ERROR  (via drill 0.4)
  Top 0.305: R13.1 26.95,28.7 v26.96,27.59
  Bottom 0.305: IC1.57 27.03,27.51
  Bottom 0.406: 27.03,27.51 v26.96,27.59
LED_OK  (via drill 0.4)
  Top 0.305: 29.34,28.54 30.13,29.34 R14.1 | 29.34,28.54 28.86,28.07 v28.7,28.07 | 29.34,28.54
  Bottom 0.305: IC1.58 27.82,27.18 v28.7,28.07
LED_PWR
  Bottom 0.305: IC1.32 20.57,9.14 19.34,7.91 19.34,7.59 R2.1
LED_RX1
  Bottom 0.406: IC1.19 31.04,8.43 32.35,7.11 R3.1
LED_RX2
  Bottom 0.406: IC1.18 31.84,8.74 32.83,7.75 33.62,7.75 34.26,7.11 LED2.K
LED_TX1
  Bottom 0.406: IC1.17 32.81,9.67 33.78,8.7 34.73,7.75 36.48,6 R4.1
LED_TX2
  Bottom 0.406: IC1.16 34.64,9.11 36.16,7.59 39.02,7.59 39.34,7.27 LED3.K
MISO
  Bottom 0.305: IC1.3 35.41,22.08 36.72,23.38 36.72,25.45 35.69,26.48 35.69,30.29 34.89,31.08 34.89,34.26 32.99,36.16 JP2.1
N$1  (via drill 0.4)
  Top 0.305: v32.83,32.04 32.99,32.04 33.46,32.51 33.46,33.78 35.05,35.37 37.75,35.37 38.07,35.69 JP2.5
  Bottom 0.305: SJ1.2 30.92,32.99 31.88,32.04 v32.83,32.04
N$2  (via drill 0.8)
  Top 0.813: v47.28,14.73 47.28,17.43 48.55,18.7 48.7,18.7 48.71,18.7 X1.1
  Bottom 0.813: L1.1 46.64,14.1 v47.28,14.73 | v47.28,14.73
N$3
  Top 0.406: R16.2 24.89,17.43 23.3,19.02 C22.2 | T2.4 25.69,15.21 25.37,15.53 R16.2 | R16.2
N$4
  Bottom 0.305: IC1.4 33.41,21.29 33.15,21.56 33.15,23.86 33.62,24.34 34.26,24.97 34.26,29.81 33.62,30.45 33.62,33.62 32.83,34.42 30.13,34.42 | 30.13,34.42 SJ1.3 | 30.13,34.42
N$5  (via drill 0.5)
  Top 0.406: v8.86,22.83 REL1.4
  Bottom 0.406: R12.2 v8.86,22.83
N$6  (via drill 0.6)
  Top 0.406: REL1.8 16.48,16.48
  Top 0.61: v16.48,14.57 REL1.8
  Bottom 0.61: 12.51,12.35 12.51,12.19 | T1.3 14.26,9.49 14.26,10.45 12.51,12.19 | 12.51,12.19 | v16.48,14.57 13.78,14.57 12.51,13.3 12.51,12.35 | D1.A 12.51,12.35
N$7
  Bottom 0.61: T1.1 16.48,10.44 16.16,10.76 15.68,10.76 14.57,11.87 14.57,12.51 | 14.57,12.51 | R1.2 14.57,12.51
N$8
  Bottom 0.406: IC1.23 27.82,7.36 28.23,6.95 29.34,6.95 | 29.34,6.95 Q2.2 | C2.1 29.55,6.74 29.34,6.95
N$9
  Bottom 0.406: R1.1 16.95,12.83 17.55,13.42 IC1.35
N$10
  Bottom 0.406: IC1.24 27.03,7.35 26.64,6.95 24.57,6.95 | Q2.1 24.57,6.95 | C1.1 24.36,6.74 24.57,6.95
N$11  (via drill 0.4)
  Top 0.305: IC6.28 37.67,18.15 40.29,15.53 | 40.29,15.53 Q1.2 | v40.29,14.57 40.29,15.53
  Bottom 0.406: C4.1 40.29,12.99 v40.29,14.57
N$12
  Top 0.305: R13.2 27.43,31.88 LED4.A
N$13  (via drill 0.4)
  Top 0.305: 36.32,15.05 v37.75,15.05 36.32,15.05 | 36.32,15.05 35.85,15.53 Q1.1 | 36.32,15.05 36,15.37 36,16 36.87,16.87 IC6.27
  Bottom 0.305: v37.75,15.05 38.07,14.73 38.07,10.76 38.23,10.6 C3.1
N$14
  Top 0.305: R14.2 30.77,31.88 31.88,30.77 LED5.A
N$15
  Bottom 0.406: R2.2 20.61,3.78 LED1.A
N$16  (via drill 0.4)
  Top 0.305: v26,28.07 26,28.86 25.05,29.81 25.05,31.72 25.37,32.04 26.48,32.04 27.59,33.15 32.19,33.15 LED5.K
  Bottom 0.305: IC1.55 25.44,27.5 v26,28.07
N$17  (via drill 0.4)
  Top 0.305: v25.05,28.54 24.42,29.18 24.42,32.67 25.05,33.31 LED4.K
  Bottom 0.305: IC1.54 24.64,28.13 v25.05,28.54
N$18  (via drill 0.5)
  Top 0.406: v11.08,27.27 IC5.8
  Bottom 0.406: v11.08,27.27 10.76,26.96 R11.2
N$19
  Bottom 1.016: X1.S2 53.45,23.77 53.47,23.78 52.04,25.21 SJ2.1
N$20
  Bottom 0.813: X1.S1 53.34,11.37 53.31,11.4 52.04,10.13 SJ3.2
N$21  (via drill 0.8)
  Top 0.813: v46.8,10.29 46.64,10.13 F1.1
  Bottom 0.813: L1.2 46.64,10.45 v46.8,10.29 45.53,10.29 45.05,9.81 C7.1
N$22
  Bottom 0.61: 17.75,36.64 C15.1
  Bottom 0.813: 17.75,38.86 IC2.4 17.75,36.64 17.75,35.21 17.59,35.05 L2.2
N$23
  Top 0.305: IC6.32 40.87,20.39 41.08,20.61 47.12,20.61 47.91,21.4 | 47.91,21.4 | 47.91,21.4 48.07,21.56 48.07,25.37 44.42,29.02 44.42,30.29 44.32,30.39 IC8.1
N$24
  Top 0.305: IC6.1 46.86,21.3 47.43,21.88 47.43,25.05 45.53,26.96 | 45.53,26.96 | 45.53,26.96 42.67,29.81 42.67,31.4 42.99,31.72 IC8.2
N$25  (via drill 0.4)
  Top 0.406: IC8.4 42.67,34.26 v41.4,32.99
  Bottom 0.406: R9.2 v41.4,32.99 | R9.2 39.66,32.99 R9.2 | R10.1 R9.2
N$26  (via drill 0.4)
  Top 0.305: IC6.2 46.39,22.1 46.8,22.51 46.8,24.73 42.04,29.5 42.04,30.92 v41.88,31.08
  Top 0.406: IC8.3 43.15,32.99 41.88,31.72 v41.88,31.08
  Bottom 0.406: R9.1 41.72,31.09 v41.88,31.08
N$27
  Bottom 0.305: IC1.11 35.78,15.78 37.43,17.43 37.43,21.24 38.39,22.19 38.39,25.69 39.18,26.48 39.18,27.59 38.86,27.91 36.64,27.91 36.32,28.23 36.32,30.61 35.53,31.4 JP2.3
N$28  (via drill 0.4)
  Top 0.305: v42.67,17.11 39.66,17.11 39.27,17.5 IC6.30
  Bottom 0.305: v42.67,17.11 42.35,16.8 42.35,13.46 42.2,12.83 | 42.2,12.83 R5.1 | C5.1 40.93,10.92 42.2,12.19 42.2,12.83 | 42.2,12.83
N$29
  Bottom 0.305: JP2.4 34.26,38.07 32.35,38.07 31.72,37.43 31.72,36.48 34.26,33.94 34.26,30.77 35.05,29.97 35.05,26.16 36.08,25.13 36.08,23.54 35.41,22.87 IC1.2
N$30
  Bottom 0.406: C12.1 29.97,27.91 30.97,26.91 IC1.62
N$31  (via drill 0.4)
  Top 0.305: IC6.8 43.68,26.9 45.69,24.89 v45.69,24.42
  Bottom 0.305: 48.7,23.94 R7.2 | v45.69,24.42 48.23,24.42 48.7,23.94 | 48.7,23.94
N$32  (via drill 0.4)
  Top 0.305: IC6.7 43.53,26.1 v43.94,25.69
  Bottom 0.305: R6.2 54.26,19.34 53.78,19.81 | 53.78,19.81 | 53.78,19.81 53.63,19.97 50.45,19.97 50.13,20.29 50.13,26.16 48.86,27.43 48.86,28.38 48.07,29.18 46.64,29.18 43.94,26.64 v43.94,25.69 43.94,26.95 R8.1
N$33
  Bottom 0.406: R4.2 37.75,3.78 LED3.A
N$34
  Bottom 0.406: R3.2 32.67,3.78 LED2.A
N$37  (via drill 0.4)
  Top 0.305: IC6.5 43.22,24.5 43.62,24.1 v43.62,23.94
  Bottom 0.305: R8.2 42.2,25.21 43.47,23.94 v43.62,23.94
N$38  (via drill 0.4)
  Top 0.406: IC6.6 43.22,25.3 43.78,24.73 v44.26,24.73
  Bottom 0.406: v44.26,24.73 44.42,24.73 45.69,26 46.01,26 C10.2
PWREN  (via drill 0.4)
  Top 0.305: R16.1 27.27,17.43 27.59,17.75 v28.7,17.75 | v27.43,24.1 31.4,28.07 33.31,28.07 34.73,29.5 39.81,29.5 40.07,29.24 IC6.10
  Bottom 0.305: v28.7,17.75 29.97,19.02 29.97,23.78 29.34,24.42 27.75,24.42 v27.43,24.1
RESET  (via drill 0.4)
  Top 0.305: R15.2 30.76,35.21 30.77,35.21 | R15.2 28.54,35.21 | 28.54,35.21 C18.1 | R15.2 28.55,35.21 28.54,35.21 | 28.54,35.21 28.38,35.21 27.75,34.58 v27.43,34.26
  Bottom 0.305: 29.65,30.92 30.61,30.92 31.88,29.65 33.15,29.65 33.62,29.18 33.62,28.07 33.62,25.13 32.51,24.02 32.51,20.92 33.15,20.29 33.15,14.73 30.24,11.82 IC1.20 | v27.43,34.26 27.43,34.1 27.43,31.24 27.75,30.92 29.65,30.92 | 29.65,30.92 SJ1.1
RXCAN  (via drill 0.4)
  Top 0.305: IC7.2 19.02,24.73 18.38,24.1 18.38,9.97 20.29,8.06 v20.29,7.75 | v20.29,7.75
  Bottom 0.305: IC1.31 21.36,8.66 20.29,7.59 v20.29,7.75
SW1  (via drill 0.4)
  Top 0.305: JP1.2 49.02,29.34 49.02,27.43 49.97,26.48 49.97,21.72 52.04,19.65 52.04,15.21 50.45,13.62 33.94,13.62 33.46,13.14 v32.99,13.14 | JP1.2 | JP1.2 JP4.1
  Bottom 0.406: IC1.14 33.19,13.35 v32.99,13.14
SW2  (via drill 0.4)
  Top 0.305: JP1.4 50.13,27.59 50.61,27.11 50.61,22.03 52.67,19.97 52.67,14.89 50.77,12.99 36.64,12.99 v36.32,12.67 | JP1.4 | JP1.4 | JP1.4 | JP1.4 JP4.2
  Bottom 0.406: v36.32,12.67 | IC1.15 36.2,12.55 v36.32,12.67
TXCAN  (via drill 0.4)
  Top 0.305: IC7.3 20.29,25.05 19.02,23.78 19.02,10.29 19.34,9.97 20.76,8.54 21.24,8.06 v21.24,7.27
  Bottom 0.305: v21.24,7.27 21.24,7.59 22.15,8.5 IC1.30
V+  (via drill 0.6)
  Top 0.406: IC5.3 13.94,29.81 13.3,30.45 13.3,32.99 | IC7.8 17.75,32.99 v15.53,32.99 13.3,32.99 | 13.3,32.99 C17.1
  Bottom 0.813: C16.1 19.65,32.99 17.75,32.99 | 17.75,32.99 L2.1 | 17.75,32.99 16.95,32.99 v15.53,32.99
VCC  (via drill 0.4)
  Top 0.305: 42.2,23.62 42.27,23.7 IC6.4 | 39.27,26.39 39.27,26.41 | 42.28,22.9 IC6.3 42.27,22.9 42.2,22.99 42.28,22.9
  Top 0.406: 27.27,13.94 28.07,13.94 31.24,17.11 35.69,17.11 36.07,17.49 IC6.26 36.07,20.83 37.27,22.03 40.45,22.03 41.4,22.99 | IC6.11 39.27,26.41 39.02,26.16 37.91,26.16 37.67,26.4 IC6.13 | 41.4,22.99 42.2,22.99 | 41.4,23.62 42.2,23.62 | 41.4,23.62 41.08,23.94 41.08,25.37 | 41.08,25.37 41.08,26.16 | 41.08,26.16 | 41.08,26.16 39.5,26.16 39.27,26.39 | 41.08,26.16 41.08,27.11 41.56,27.59 41.56,29.02 41.24,29.34 41.24,30.13 40.93,30.45 IC8.8 37.43,30.45 36.48,31.4 | 41.4,22.99 41.4,23.62 | 41.4,23.62 | IC6.3 43.22,22.9 v43.47,22.99 | 36.48,31.4 | 36.48,31.4 C19.1 | 41.08,25.37 41.08,25.69 v40.93,25.84 | v40.93,25.84
  Top 0.61: T2.1 27.27,11.4 27.27,12.67 | T2.3 27.27,13.94 27.27,12.67 | 27.27,12.67 27.27,11.72 | F1.2 34.26,10.13 31.72,12.67 30.92,12.67 | 27.27,12.67 T2.2 | 27.27,12.67 30.92,12.67 | 30.92,12.67 C20.1
  Bottom 0.406: 45.21,15.84 45.21,15.05 44.1,13.94 44.1,12.67 | v43.47,22.99 | v43.47,22.99 43.31,22.83 43.31,17.75 45.21,15.84 | 46.16,15.84 IC4.14 45.21,15.84 | 44.1,12.67 R5.2 | 44.1,12.67 44.1,12.51 42.99,11.4 C6.1 | R10.2 37.59,29.65 37.91,29.34 40.77,29.34 41.08,29.02 | 42.3,29.6 C11.1 42.3,29.55 42.2,29.02 41.08,29.02 | 41.08,29.02 41.08,26 v40.93,25.84 | 41.08,29.02

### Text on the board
Top: v1.3 | top | USB2CAN
Bottom: (c) Fabian Greif | bot
tPlace: Program | Taster
tNames: Status | TX | RX
Eagle3D: 6 15 | 1 15 | 7 100 | V4 -10 | 5 6 | V3 0 | 2 4 | V1 0 | 4 5 | V2 0 | 3 8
